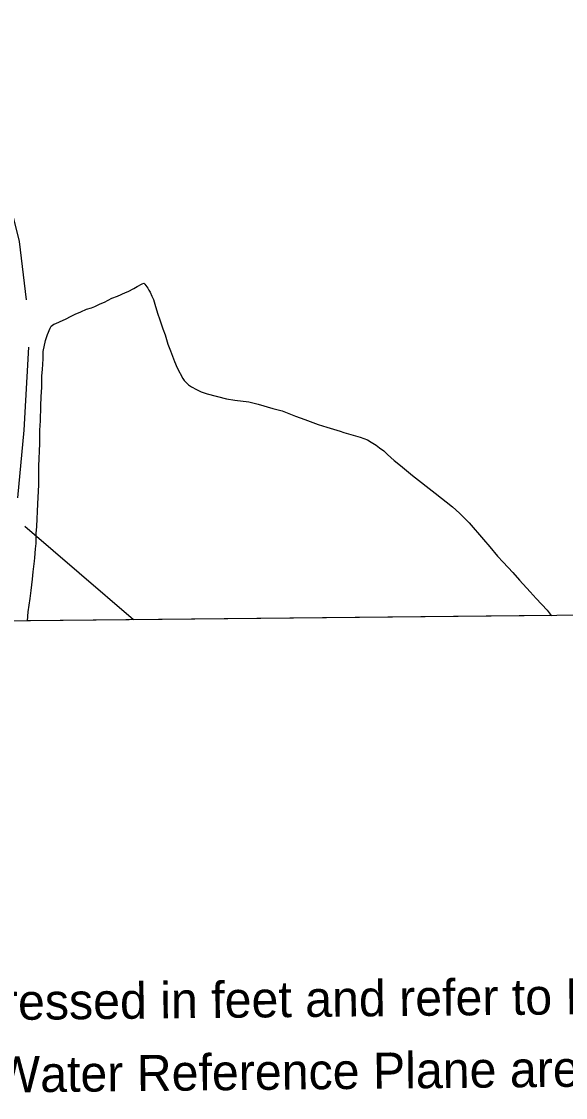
# Model space of a CAD drawing. Extents: x 3625074 to 3663148, y 511451 to 537151.
# Drawn here: x 3630544 to 3631795, y 515777 to 518251 of the extents above; entities that cross this region are included whole.
import ezdxf

# ---------------------------------------------------------------- set-up
doc = ezdxf.new("R2010")
doc.units = 0
for name, color, linetype in [('V-ANNO-NOTE', 7, 'Continuous'), ('V-GRID-FRAM', 7, 'Continuous'), ('V-SITE-VEGE', 7, 'Continuous'), ('V-TOPO-SHOR', 7, 'Continuous')]:
    doc.layers.add(name, color=color, linetype=linetype)

msp = doc.modelspace()

# ---------------------------------------------------------------- linework, layer by layer
at = {"layer": 'V-GRID-FRAM'}
msp.add_lwpolyline([(3629129.4, 535042.1), (3660791.6, 535359.9), (3660982, 517178), (3629304, 516860), (3629129.4, 535042.1)], dxfattribs=at)
at = {"layer": 'V-SITE-VEGE'}
for p, q in [((3630810.5, 517640.9), (3630821.7, 517647.4)), ((3630821.7, 517647.4), (3630825.5, 517648.8)), ((3630825.5, 517648.8), (3630828, 517646.3)), ((3630828, 517646.3), (3630834.5, 517637.6)), ((3630764.9, 517619.4), (3630783.6, 517627.3)), ((3630783.6, 517627.3), (3630789.2, 517629.9)), ((3630789.2, 517629.9), (3630802.4, 517636.4)), ((3630802.4, 517636.4), (3630810.5, 517640.9)), ((3630834.5, 517637.6), (3630837.1, 517633.2)), ((3630837.1, 517633.2), (3630839.7, 517628.2)), ((3630839.7, 517628.2), (3630843.6, 517618.8)), ((3630713, 517595.2), (3630725.5, 517601.1)), ((3630725.5, 517601.1), (3630734.9, 517605.6)), ((3630734.9, 517605.6), (3630751.7, 517614.1)), ((3630751.7, 517614.1), (3630764.9, 517619.4)), ((3630843.6, 517618.8), (3630847.5, 517611.3)), ((3630847.5, 517611.3), (3630850.9, 517600.7)), ((3630850.9, 517600.7), (3630856.9, 517580)), ((3630646.7, 517567), (3630657.3, 517572.2)), ((3630657.3, 517572.2), (3630667.9, 517578)), ((3630667.9, 517578), (3630680.4, 517583.3)), ((3630680.4, 517583.3), (3630693.6, 517589.2)), ((3630693.6, 517589.2), (3630704.9, 517591.9)), ((3630704.9, 517591.9), (3630713, 517595.2)), ((3630856.9, 517580), (3630862.2, 517565)), ((3630609.9, 517545.5), (3630612.3, 517550)), ((3630612.3, 517550), (3630618.6, 517554.5)), ((3630618.6, 517554.5), (3630623.6, 517556.5)), ((3630623.6, 517556.5), (3630631.7, 517560.4)), ((3630631.7, 517560.4), (3630646.7, 517567)), ((3630862.2, 517565), (3630869.5, 517543.7)), ((3630599.7, 517517), (3630603.9, 517531)), ((3630603.9, 517531), (3630609.9, 517545.5)), ((3630869.5, 517543.7), (3630874.7, 517529.9)), ((3630874.7, 517529.9), (3630880.8, 517508.6)), ((3630594.4, 517491.7), (3630599.7, 517517)), ((3630880.8, 517508.6), (3630886.7, 517493.6)), ((3630592.6, 517450.8), (3630594.1, 517474.7)), ((3630594.1, 517474.7), (3630594.4, 517491.7)), ((3630886.7, 517493.6), (3630895.9, 517468.6)), ((3630591, 517435.6), (3630592.6, 517450.8)), ((3630895.9, 517468.6), (3630902.5, 517454.2)), ((3630902.5, 517454.2), (3630915.5, 517429.8)), ((3630590.8, 517409.2), (3630591, 517435.6)), ((3630915.5, 517429.8), (3630918.1, 517425.5)), ((3630918.1, 517425.5), (3630928.4, 517414.9)), ((3630589.3, 517388.3), (3630590.8, 517409.2)), ((3630928.4, 517414.9), (3630935.4, 517410.6)), ((3630935.4, 517410.6), (3630946.8, 517404.5)), ((3630946.8, 517404.5), (3630957.6, 517399.1)), ((3630957.6, 517399.1), (3630970.9, 517394.2)), ((3630588.4, 517366.3), (3630589.3, 517388.3)), ((3630970.9, 517394.2), (3631015.8, 517383)), ((3631015.8, 517383), (3631034.8, 517380.2)), ((3631034.8, 517380.2), (3631067, 517376.4)), ((3631067, 517376.4), (3631088.5, 517370.4)), ((3630587.7, 517332.2), (3630588.4, 517366.3)), ((3631088.5, 517370.4), (3631122, 517360.9)), ((3631122, 517360.9), (3631143.6, 517355)), ((3631143.6, 517355), (3631174, 517342.9)), ((3630586.8, 517310.8), (3630587.7, 517332.2)), ((3631174, 517342.9), (3631195.5, 517335.7)), ((3631195.5, 517335.7), (3631226.6, 517324.3)), ((3630586.7, 517280), (3630586.8, 517310.8)), ((3631226.6, 517324.3), (3631246.2, 517317.7)), ((3631246.2, 517317.7), (3631276.6, 517308.8)), ((3631276.6, 517308.8), (3631285.5, 517305.8)), ((3631285.5, 517305.8), (3631322.9, 517295.1)), ((3630584.5, 517228.3), (3630586.7, 517280)), ((3631322.9, 517295.1), (3631339.3, 517288.4)), ((3631339.3, 517288.4), (3631348.3, 517283.5)), ((3631348.3, 517283.5), (3631359.7, 517276.8)), ((3631359.7, 517276.8), (3631367.4, 517270.6)), ((3631367.4, 517270.6), (3631376.9, 517263.2)), ((3631376.9, 517263.2), (3631385.9, 517255.2)), ((3631385.9, 517255.2), (3631401.3, 517241)), ((3630584.2, 517210), (3630584.5, 517228.3)), ((3631401.3, 517241), (3631415.3, 517229.9)), ((3631415.3, 517229.9), (3631442.8, 517207)), ((3630583.9, 517185.4), (3630584.2, 517210)), ((3631442.8, 517207), (3631495.1, 517166.4)), ((3630581.6, 517141.3), (3630583.9, 517185.4)), ((3631495.1, 517166.4), (3631535.4, 517134.9)), ((3630579.3, 517089.6), (3630581.6, 517141.3)), ((3631535.4, 517134.9), (3631551.4, 517120.1)), ((3631551.4, 517120.1), (3631573.2, 517097.8)), ((3630578.3, 517073.2), (3630579.3, 517089.6)), ((3631573.2, 517097.8), (3631606.6, 517059.3)), ((3630578.1, 517050.5), (3630578.3, 517073.2)), ((3631606.6, 517059.3), (3631620.7, 517042.5)), ((3630574.8, 517017.7), (3630576.4, 517037.9)), ((3630576.4, 517037.9), (3630578.1, 517050.5)), ((3631620.7, 517042.5), (3631638.7, 517021.4)), ((3630571, 516985.5), (3630574.4, 517009.5)), ((3630574.4, 517009.5), (3630574.8, 517017.7)), ((3631638.7, 517021.4), (3631651.6, 517007.8)), ((3631651.6, 517007.8), (3631673.4, 516983.6)), ((3630569.4, 516968.5), (3630571, 516985.5)), ((3631673.4, 516983.6), (3631689.4, 516966.2)), ((3630566.7, 516942.6), (3630569.4, 516968.5)), ((3631689.4, 516966.2), (3631713.2, 516938.9)), ((3630563.9, 516923.6), (3630566.7, 516942.6)), ((3631713.2, 516938.9), (3631727.3, 516924)), ((3630560, 516893.3), (3630563.9, 516923.6)), ((3631727.3, 516924), (3631752.4, 516896.8)), ((3630558, 516872.6), (3630560, 516893.3)), ((3631763.2, 516884.7), (3630558, 516872.6)), ((3631752.4, 516896.8), (3631759.4, 516888.1)), ((3631759.4, 516888.1), (3631763.2, 516884.7))]:
    msp.add_line(p, q, dxfattribs=at)
at = {"layer": 'V-TOPO-SHOR'}
for points in [[(3631514.1, 519676.7), (3631319.9, 519457.1), (3631143.2, 519261), (3630964, 519065.8), (3630766.5, 518847.7), (3630531, 518594.7), (3630400.7, 518447.4), (3630343.5, 518388.1), (3630309.5, 518347.3), (3630299.4, 518327.7), (3630299.2, 518300.7), (3630315.2, 518266), (3630388.6, 518125), (3630469.1, 517962.5), (3630510, 517862.8), (3630539.2, 517745.1), (3630555.1, 517610.4)], [(3630560.6, 517502), (3630549.8, 517310.8), (3630535.1, 517155)], [(3630801.9, 516875.1), (3630551.6, 517089.7)]]:
    msp.add_lwpolyline(points, dxfattribs=at)

# ---------------------------------------------------------------- texts
at = {"layer": 'V-ANNO-NOTE'}
for s, p in [('All elevations are expressed in feet and refer to North American Vertical Datum of 1988.', (3629444.7, 515944.1)), ('Contours below Low Water Reference Plane are expressed in feet at 5 and 10 ft. intervals.', (3629446.4, 515777.5))]:
    msp.add_text(s, height=83, rotation=0.575, dxfattribs=at).set_placement(p)

doc.saveas('drawing.dxf')
